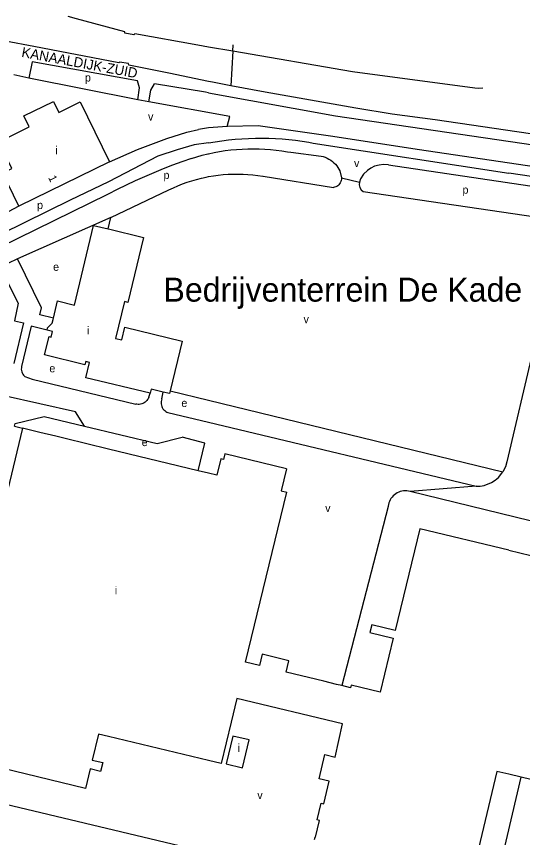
# Model space of a CAD drawing. Extents: x 162804 to 165059, y 381530 to 382901.
# Drawn here: x 163254 to 163506.9, y 382442.3 to 382852.8 of the extents above; entities that cross this region are included whole.
import ezdxf

# ---------------------------------------------------------------- set-up
doc = ezdxf.new("R2010")
doc.units = 0
for name, color, linetype in [('BLT_Basislijn', 7, 'Continuous'), ('BLT_Bebouwing', 7, 'Continuous'), ('BLT_Centroide', 7, 'Continuous'), ('BLT_Huisnummer', 7, 'Continuous'), ('BLT_Sport_parknaam', 7, 'Continuous'), ('BLT_Straatnaam', 7, 'Continuous'), ('BLT_Vlakafsluiter', 7, 'Continuous')]:
    doc.layers.add(name, color=color, linetype=linetype)

msp = doc.modelspace()

# ---------------------------------------------------------------- linework, layer by layer
at = {"layer": 'BLT_Basislijn'}
for p, q in [((163284.01, 382851.66), (163279.82, 382852.8)), ((163305.26, 382829.61), (163262.7, 382837.7)), ((163350, 382837.47), (163344.68, 382838.39)), ((163362.15, 382835.39), (163350, 382837.47)), ((163421.96, 382825.13), (163362.15, 382835.39)), ((163314.65, 382811.1), (163260.28, 382821.96)), ((163351.91, 382819.96), (163350, 382820.35)), ((163350, 382814.61), (163348.56, 382814.87)), ((163320.19, 382810.11), (163314.65, 382811.1)), ((163525.18, 382791.94), (163463.22, 382801.03)), ((163350, 382797.13), (163344.94, 382796.24)), ((163350, 382789.54), (163342.88, 382788.54)), ((163391.12, 382784.87), (163406.36, 382782.96)), ((163439.97, 382778.56), (163515.12, 382767.51)), ((163415.61, 382775.62), (163416.42, 382772.08)), ((163377.25, 382772.9), (163412.39, 382767.2)), ((163299.49, 382763.84), (163245.82, 382737.43)), ((163255.22, 382757.98), (163219.01, 382738.59)), ((163301.17, 382752.29), (163254.47, 382731.57)), ((163258.23, 382672.74), (163261.95, 382671.55)), ((163261.95, 382671.55), (163313.7, 382659.05)), ((163320.12, 382662.41), (163320.89, 382664.41)), ((163326.63, 382661.63), (163327.36, 382665.01)), ((163330.78, 382665.69), (163350, 382661.03)), ((163350, 382661.03), (163497.09, 382625.15)), ((163329.62, 382654.83), (163350, 382649.95)), ((163253.08, 382647.9), (163257.08, 382646.93)), ((163439.68, 382607.76), (163416.54, 382518.29)), ((163494.04, 382420.61), (163506.23, 382472.49)), ((163213.07, 382467.42), (163350, 382434.88))]:
    msp.add_line(p, q, dxfattribs=at)
for points in [[(163344.68, 382838.39), (163313.21, 382844.06), (163312.72, 382843.59), (163308.26, 382844.47), (163308.11, 382845.13), (163284.01, 382851.66)], [(163262.7, 382837.7), (163220.15, 382845.79), (163195.06, 382850.97)], [(163314.57, 382820.57), (163261.86, 382830.14), (163260.28, 382821.96)], [(163330.12, 382824.41), (163310.24, 382828.46), (163310.04, 382829.2), (163305.57, 382830.01), (163305.26, 382829.61)], [(163260.28, 382821.96), (163252.7, 382823.52)], [(163350, 382820.35), (163330.12, 382824.41)], [(163485.15, 382816.81), (163483.15, 382816.91), (163421.96, 382825.13)], [(163314.65, 382811.1), (163315.59, 382817.02), (163314.57, 382820.57)], [(163320.19, 382810.11), (163321.22, 382816), (163323.01, 382819.05)], [(163348.56, 382814.87), (163323.01, 382819.05)], [(163361.21, 382818.16), (163351.91, 382819.96)], [(163350, 382814.61), (163413.51, 382803.18), (163537.13, 382784.9)], [(163423.67, 382806.99), (163378.29, 382814.86), (163361.21, 382818.16)], [(163487, 382816.95), (163485.15, 382816.81)], [(163359.37, 382797.83), (163360.61, 382802.83), (163320.19, 382810.11)], [(163463.22, 382801.03), (163441.72, 382804), (163423.67, 382806.99)], [(163993.07, 382706.91), (163535.27, 382774.35), (163455.47, 382786.14), (163410.94, 382792.86), (163374.85, 382798.03), (163359.37, 382797.83)], [(163300.53, 382780.1), (163314.56, 382786.26), (163329.21, 382791.76), (163339.13, 382794.96), (163344.94, 382796.24)], [(163359.37, 382797.83), (163350, 382797.13)], [(163350, 382789.54), (163353.31, 382790.12), (163356.64, 382790.62), (163359.98, 382791.04), (163363.32, 382791.39), (163366.68, 382791.65), (163370.04, 382791.83), (163373.4, 382791.93), (163376.76, 382791.96), (163380.13, 382791.9), (163383.49, 382791.76), (163386.84, 382791.55), (163390.2, 382791.25), (163393.54, 382790.87), (163396.87, 382790.42), (163400.19, 382789.88), (163402.3, 382789.5)], [(163342.88, 382788.54), (163334.37, 382786.16), (163324.71, 382782.9), (163300, 382770.11), (163280.94, 382760.98), (163246.71, 382744.11), (163245.68, 382743.43), (163223.18, 382732.48), (163214.74, 382728.24)], [(163350, 382784.18), (163352.77, 382784.77), (163355.56, 382785.28), (163358.36, 382785.71), (163361.18, 382786.06), (163364, 382786.33), (163366.83, 382786.52), (163369.66, 382786.64), (163372.49, 382786.67), (163375.33, 382786.62), (163378.16, 382786.49), (163380.99, 382786.28), (163383.81, 382785.99), (163386.62, 382785.63), (163389.42, 382785.18), (163391.12, 382784.87)], [(163402.3, 382789.5), (163500, 382774.52)], [(163341.43, 382781.84), (163336.69, 382780.16), (163331.98, 382778.4), (163327.29, 382776.56), (163322.63, 382774.66), (163318.01, 382772.67), (163313.41, 382770.62), (163308.85, 382768.49), (163304.33, 382766.29), (163299.84, 382764.02), (163299.49, 382763.84)], [(163341.43, 382781.84), (163344.14, 382782.67), (163346.88, 382783.42), (163349.63, 382784.1), (163350, 382784.18)], [(163406.36, 382782.96), (163407.36, 382782.71), (163408.33, 382782.39), (163409.27, 382781.98), (163410.19, 382781.51), (163411.06, 382780.97), (163411.89, 382780.36), (163412.66, 382779.68), (163413.38, 382778.95), (163414.05, 382778.17), (163414.65, 382777.33), (163415.18, 382776.45), (163415.61, 382775.62)], [(163439.97, 382778.56), (163437.51, 382778.78), (163435.3, 382778.47), (163432.98, 382777.9), (163431.08, 382776.97), (163429.39, 382775.8), (163427.4, 382773.91), (163426.01, 382771.57), (163425.36, 382769.97)], [(163350, 382772.72), (163352.44, 382773.13), (163354.89, 382773.47), (163357.36, 382773.73), (163359.82, 382773.91), (163362.3, 382774.01), (163364.77, 382774.03), (163367.25, 382773.97), (163369.72, 382773.83), (163372.18, 382773.61), (163374.64, 382773.31), (163377.09, 382772.93), (163377.25, 382772.9)], [(163666.72, 382750), (163500, 382774.52)], [(163330.19, 382766.1), (163332.42, 382767.16), (163334.69, 382768.15), (163336.99, 382769.06), (163339.32, 382769.9), (163341.68, 382770.67), (163344.06, 382771.35), (163346.46, 382771.96), (163348.87, 382772.49), (163350, 382772.72)], [(163416.42, 382772.08), (163416.4, 382771.45), (163416.29, 382770.83), (163416.11, 382770.23), (163415.85, 382769.65), (163415.52, 382769.11), (163415.13, 382768.62), (163414.68, 382768.18), (163414.17, 382767.8), (163414.04, 382767.72), (163412.39, 382767.2)], [(163425.36, 382769.97), (163425.25, 382768.68), (163425.6, 382767.33), (163426.26, 382766.16), (163427.26, 382765.28), (163519.12, 382751.86), (163517.34, 382741.19), (163524.73, 382739.51)], [(163301.17, 382752.29), (163330.19, 382766.1)], [(163299.86, 382746.58), (163301.17, 382752.29)], [(163524.73, 382739.51), (163499.07, 382630.19), (163498.36, 382627.64), (163497.09, 382625.15)], [(163249.72, 382729.24), (163245.69, 382727.26), (163254.86, 382709.41), (163253.04, 382700.65), (163257.5, 382699.61), (163252.69, 382679.34)], [(163254.47, 382731.57), (163249.72, 382729.24)], [(163272.52, 382702.03), (163265.7, 382703.66), (163266.57, 382707.08), (163254.47, 382731.57)], [(163269.3, 382695.97), (163261.34, 382697.93), (163256.56, 382677.8)], [(163256.56, 382677.8), (163256.47, 382677.15), (163256.46, 382676.49), (163256.54, 382675.83), (163256.69, 382675.19), (163256.91, 382674.57), (163257.21, 382673.99), (163257.58, 382673.44), (163258.02, 382672.94), (163258.23, 382672.74)], [(163320.12, 382662.41), (163319.77, 382661.72), (163319.5, 382661.25), (163319.17, 382660.74), (163318.76, 382660.4), (163318.3, 382659.96), (163317.79, 382659.6), (163317.24, 382659.29), (163316.65, 382659.07), (163316.04, 382658.91), (163315.42, 382658.84), (163314.79, 382658.84), (163314.16, 382658.93), (163313.7, 382659.05)], [(163326.63, 382661.63), (163326.43, 382661.01), (163326.31, 382660.38), (163326.27, 382659.73), (163326.31, 382659.08), (163326.43, 382658.45), (163326.62, 382657.83), (163326.9, 382657.24), (163327.24, 382656.69), (163327.64, 382656.18), (163328.11, 382655.73), (163328.63, 382655.34), (163329.19, 382655.02), (163329.62, 382654.83)], [(163253.08, 382647.9), (163253.44, 382649.38), (163267.8, 382652.86), (163288.01, 382648.03)], [(163288.01, 382648.03), (163324.35, 382639.35), (163336.85, 382642.43)], [(163350, 382649.95), (163483.81, 382617.91)], [(163344.87, 382625.68), (163348.19, 382639.51), (163336.85, 382642.43)], [(163483.81, 382617.91), (163485.66, 382618.06), (163487.81, 382618.29), (163491.41, 382619.77), (163493.31, 382620.95), (163494.96, 382622.37), (163497.09, 382625.15)], [(163450.78, 382615.36), (163449.96, 382615.54), (163449.13, 382615.65), (163448.29, 382615.67), (163447.45, 382615.62), (163446.62, 382615.48), (163445.81, 382615.27), (163445.02, 382614.98), (163444.27, 382614.62), (163443.55, 382614.19), (163442.87, 382613.69), (163442.25, 382613.12), (163441.68, 382612.51), (163441.17, 382611.84), (163440.73, 382611.12), (163440.36, 382610.37), (163440.07, 382609.59), (163439.85, 382608.78), (163439.7, 382607.95), (163439.68, 382607.76)], [(163591.01, 382563.83), (163590.81, 382567.55), (163589.61, 382572.98), (163586.59, 382577.82), (163582.17, 382581.94), (163577.59, 382584.32), (163450.78, 382615.36)]]:
    msp.add_lwpolyline(points, dxfattribs=at)
at = {"layer": 'BLT_Bebouwing'}
for p, q in [((163265.66, 382644.85), (163257.08, 382646.93)), ((163273.68, 382642.91), (163265.66, 382644.85)), ((163356.19, 382631.7), (163354.19, 382623.42)), ((163354.19, 382623.42), (163350, 382624.44)), ((163368.49, 382530.01), (163389.07, 382614.98)), ((163455.55, 382596.73), (163443.21, 382545.81)), ((163500, 382585.97), (163455.55, 382596.73)), ((163500, 382585.97), (163545.42, 382574.98)), ((163442.3, 382542.06), (163435.75, 382515.01)), ((163520.03, 382469.15), (163506.23, 382472.49))]:
    msp.add_line(p, q, dxfattribs=at)
for points in [[(163255.22, 382757.98), (163247.16, 382774.53), (163251.74, 382776.76), (163245.19, 382790.18), (163260.38, 382797.59), (163257.72, 382803.04), (163272.56, 382810.28), (163275.22, 382804.83), (163285.92, 382810.05), (163300.53, 382780.1)], [(163300.53, 382780.1), (163255.22, 382757.98)], [(163272.52, 382702.03), (163274.6, 382710.58), (163282.98, 382708.54), (163292.57, 382748.35), (163299.86, 382746.58)], [(163299.86, 382746.58), (163300, 382746.55), (163317.58, 382742.29), (163316.4, 382737.43), (163309.71, 382709.84), (163307.96, 382710.26), (163303.52, 382691.87)], [(163269.3, 382695.97), (163269.61, 382697.11), (163271.83, 382699.41), (163272.36, 382701.35), (163272.52, 382702.03)], [(163288.64, 382680.31), (163288.25, 382678.7), (163268.06, 382683.58), (163270.29, 382692.76), (163271.39, 382692.49), (163272.06, 382695.3), (163269.3, 382695.97)], [(163303.52, 382691.87), (163306.7, 382691.1), (163308.24, 382697.44), (163336.81, 382690.5), (163330.78, 382665.69)], [(163320.89, 382664.41), (163288.71, 382672.21), (163290.57, 382679.84), (163288.64, 382680.31)], [(163327.36, 382665.01), (163321.38, 382666.46), (163320.89, 382664.41)], [(163330.78, 382665.69), (163330.43, 382664.26), (163327.36, 382665.01)], [(163257.08, 382646.93), (163235.68, 382558.47)], [(163278.31, 382641.79), (163273.68, 382642.91)], [(163344.87, 382625.68), (163300, 382636.54), (163278.31, 382641.79)], [(163388.92, 382626.67), (163358.12, 382634.12), (163357.46, 382631.39), (163356.19, 382631.7)], [(163350, 382624.44), (163344.87, 382625.68)], [(163388.92, 382626.67), (163386.26, 382615.66), (163389.07, 382614.98)], [(163443.21, 382545.81), (163431.54, 382548.63), (163430.63, 382544.88), (163442.3, 382542.06)], [(163407.59, 382520.47), (163388.77, 382525.06), (163390.15, 382530.74), (163376.85, 382533.98), (163375.46, 382528.31), (163368.49, 382530.01)], [(163414.01, 382518.91), (163407.59, 382520.47)], [(163416.54, 382518.29), (163414.01, 382518.91)], [(163435.75, 382515.01), (163421.32, 382518.51), (163421, 382517.2), (163416.54, 382518.29)], [(163364.14, 382511.89), (163361.28, 382500), (163356.26, 382479.42), (163350, 382480.92)], [(163403.02, 382441.4), (163403.32, 382442.56), (163403.49, 382442.52), (163405.5, 382450.85), (163404.25, 382451.15), (163406.27, 382459.52), (163407.55, 382459.21), (163410.25, 382470.48), (163405.27, 382471.71), (163408.19, 382483.84), (163413.21, 382482.6), (163416.88, 382499.12), (163364.14, 382511.89)], [(163350, 382480.92), (163300, 382492.9), (163295.1, 382494.07), (163291.86, 382481.05), (163297.14, 382479.85), (163296.09, 382475.38), (163290.81, 382476.64), (163288.5, 382466.86)], [(163366.96, 382477.23), (163370.3, 382491.13), (163362.17, 382493.06), (163358.84, 382479.17), (163366.96, 382477.23)], [(163288.5, 382466.86), (163246.71, 382476.98)], [(163506.23, 382472.49), (163500, 382474), (163494.11, 382475.43), (163484.1, 382433.33), (163481.49, 382422.35), (163436.24, 382433.33), (163417.07, 382437.99)]]:
    msp.add_lwpolyline(points, dxfattribs=at)
at = {"layer": 'BLT_Vlakafsluiter'}
for p, q in [((163362.15, 382835.39), (163361.21, 382818.16)), ((163362.15, 382835.39), (163362.3, 382838.54)), ((163416.42, 382772.08), (163425.36, 382769.97)), ((163483.81, 382617.91), (163450.78, 382615.36))]:
    msp.add_line(p, q, dxfattribs=at)
msp.add_lwpolyline([(163288.01, 382648.03), (163283.58, 382655.2), (163247.91, 382663.13)], dxfattribs=at)

# ---------------------------------------------------------------- texts
at = {"layer": 'BLT_Centroide'}
for s, p in [('p', (163288.25, 382820.26)), ('v', (163319.78, 382800.72)), ('i', (163273.45, 382783.94)), ('v', (163422.71, 382777.5)), ('p', (163327.5, 382771.52)), ('p', (163476.9, 382764.18)), ('p', (163264.33, 382756.53)), ('e', (163272.34, 382725.63)), ('v', (163397.49, 382699.46)), ('i', (163289.22, 382693.88)), ('e', (163270.47, 382674.91)), ('e', (163336.43, 382657.57)), ('e', (163316.59, 382638.02)), ('v', (163408.3, 382605.05)), ('i', (163303.17, 382563.95)), ('i', (163364.56, 382485.16)), ('v', (163374.38, 382461.56))]:
    msp.add_text(s, height=4, dxfattribs=at).set_placement(p)
at = {"layer": 'BLT_Huisnummer'}
msp.add_text('1', height=4, rotation=296.0004, dxfattribs=at).set_placement((163269.8, 382772.26))
at = {"layer": 'BLT_Sport_parknaam'}
msp.add_text('Bedrijventerrein De Kade', height=12, dxfattribs=at).set_placement((163327.47, 382710.23))
at = {"layer": 'BLT_Straatnaam'}
msp.add_text('KANAALDIJK-ZUID', height=5, rotation=349.4888, dxfattribs=at).set_placement((163256.28, 382832.61))

doc.saveas('drawing.dxf')
